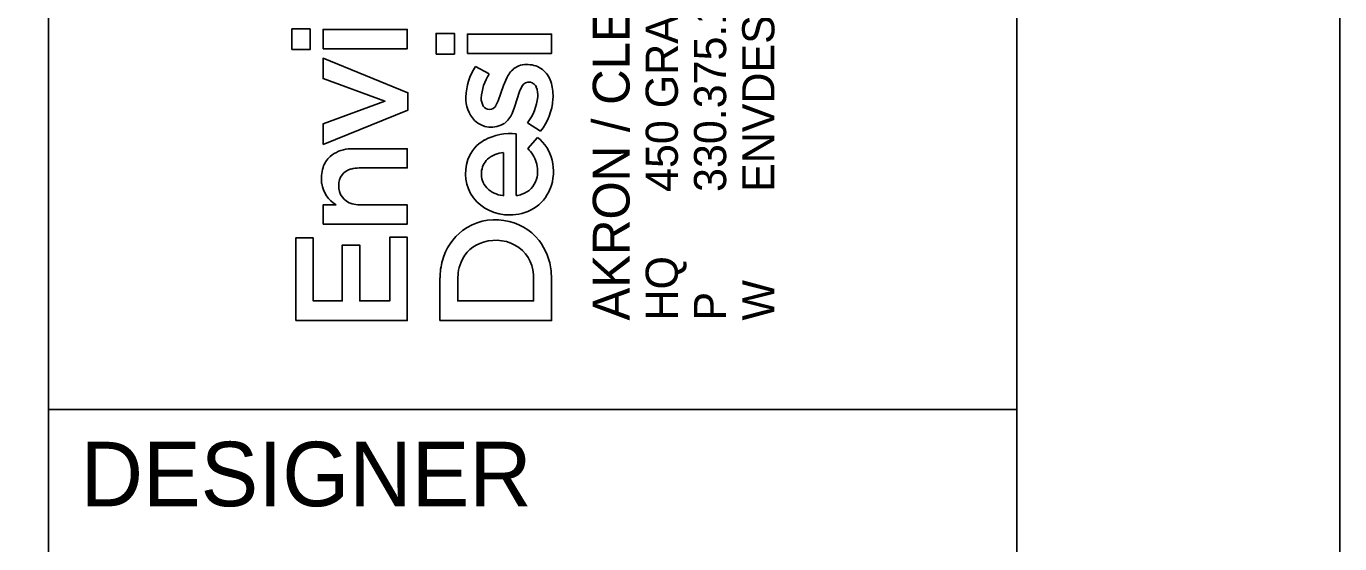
# Model space of a CAD drawing. Extents: x 0 to 34, y 0 to 22.
# Drawn here: x 31.966 to 34, y 2.292 to 3.094 of the extents above; entities that cross this region are included whole.
import ezdxf

# ---------------------------------------------------------------- set-up
doc = ezdxf.new("R2010")
doc.units = 0
for name, color, linetype in [('SH_Border', 7, 'Continuous'), ('SH_Cut_Line', 7, 'Continuous'), ('SH_Data', 7, 'Continuous')]:
    doc.layers.add(name, color=color, linetype=linetype)

msp = doc.modelspace()

# ---------------------------------------------------------------- linework, layer by layer
at = {"layer": 'SH_Border'}
for p, q in [((32, 0.5), (32, 21.5)), ((32, 2.5), (33.5, 2.5))]:
    msp.add_line(p, q, dxfattribs=at)
msp.add_lwpolyline([(1.5, 21.5), (33.5, 21.5), (33.5, 0.5), (1.5, 0.5)], close=True, dxfattribs=at)
at = {"layer": 'SH_Cut_Line'}
msp.add_lwpolyline([(0, 0), (34, 0), (34, 22), (0, 22)], close=True, dxfattribs=at)
at = {"layer": 'SH_Data'}
for p, q in [((32.3771, 3.0582), (32.3771, 3.0903)), ((32.3771, 3.0903), (32.4054, 3.0903)), ((32.4054, 3.0903), (32.4054, 3.0582)), ((32.4254, 3.0594), (32.4254, 3.0893)), ((32.4254, 3.0893), (32.5557, 3.0893)), ((32.5557, 3.0893), (32.5557, 3.0594)), ((32.6005, 3.0511), (32.6005, 3.0832)), ((32.6005, 3.0832), (32.6289, 3.0832)), ((32.6289, 3.0832), (32.6289, 3.0511)), ((32.6489, 3.0523), (32.6489, 3.0822)), ((32.6489, 3.0822), (32.7792, 3.0822)), ((32.7792, 3.0822), (32.7792, 3.0523)), ((32.4054, 3.0582), (32.3771, 3.0582)), ((32.5557, 3.0594), (32.4254, 3.0594)), ((32.7792, 3.0523), (32.6489, 3.0523)), ((32.4254, 3.0133), (32.4254, 3.0446)), ((32.4254, 3.0446), (32.5567, 2.9913)), ((32.6289, 3.0511), (32.6005, 3.0511)), ((32.6615, 3.0321), (32.6827, 3.0203)), ((32.5212, 2.978), (32.4254, 3.0133)), ((32.7048, 3.0026), (32.7104, 3.0153)), ((32.5567, 2.9913), (32.5567, 2.9644)), ((32.6967, 2.9787), (32.7048, 3.0026)), ((32.7298, 2.9933), (32.7221, 2.9688)), ((32.7334, 3.001), (32.7298, 2.9933)), ((32.4254, 2.9429), (32.5212, 2.978)), ((32.693, 2.9712), (32.6967, 2.9787)), ((32.5567, 2.9644), (32.4254, 2.9109)), ((32.7221, 2.9688), (32.7182, 2.9592)), ((32.4254, 2.9109), (32.4254, 2.9429)), ((32.7621, 2.9314), (32.742, 2.9447)), ((32.7245, 2.9275), (32.7246, 2.8319)), ((32.7423, 2.9046), (32.7577, 2.922)), ((32.4644, 2.904), (32.4729, 2.9044)), ((32.4729, 2.9044), (32.5557, 2.9044)), ((32.5557, 2.9044), (32.5557, 2.8746)), ((32.7049, 2.8318), (32.7049, 2.8983)), ((32.5557, 2.8746), (32.4814, 2.8746)), ((32.7036, 2.8317), (32.7049, 2.8318)), ((32.4254, 2.7875), (32.4254, 2.8173)), ((32.4254, 2.8173), (32.4455, 2.8173)), ((32.4822, 2.8173), (32.5557, 2.8173)), ((32.5557, 2.8173), (32.5557, 2.7876)), ((32.5557, 2.7876), (32.4254, 2.7875)), ((32.5286, 2.6683), (32.5286, 2.7672)), ((32.5286, 2.7672), (32.5557, 2.7672)), ((32.5557, 2.7672), (32.5557, 2.6379)), ((32.383, 2.6379), (32.383, 2.766)), ((32.383, 2.766), (32.4101, 2.766)), ((32.4101, 2.766), (32.4101, 2.6683)), ((32.455, 2.6683), (32.455, 2.7549)), ((32.455, 2.7549), (32.4822, 2.7549)), ((32.4822, 2.7549), (32.4822, 2.6683)), ((32.6347, 2.7118), (32.6341, 2.7023)), ((32.7785, 2.715), (32.7792, 2.7021)), ((32.6064, 2.638), (32.6064, 2.704)), ((32.6341, 2.7023), (32.6341, 2.6684)), ((32.7515, 2.6683), (32.7515, 2.7024)), ((32.7792, 2.7021), (32.7792, 2.638)), ((32.4101, 2.6683), (32.455, 2.6683)), ((32.4822, 2.6683), (32.5286, 2.6683)), ((32.6341, 2.6684), (32.7515, 2.6683)), ((32.5557, 2.6379), (32.383, 2.6379)), ((32.7792, 2.638), (32.6064, 2.638))]:
    msp.add_line(p, q, dxfattribs=at)
for points in [[(32.3771, 3.0582), (32.3771, 3.0903), (32.4054, 3.0903), (32.4054, 3.0582)], [(32.4254, 3.0594), (32.4254, 3.0893), (32.5557, 3.0893), (32.5557, 3.0594)], [(32.6005, 3.0511), (32.6005, 3.0832), (32.6289, 3.0832), (32.6289, 3.0511)], [(32.6489, 3.0523), (32.6489, 3.0822), (32.7792, 3.0822), (32.7792, 3.0523)], [(32.4254, 2.9109), (32.4254, 2.9429), (32.5212, 2.978), (32.4254, 3.0133), (32.4254, 3.0446), (32.5567, 2.9913), (32.5567, 2.9644)], [(32.383, 2.6379), (32.383, 2.766), (32.4101, 2.766), (32.4101, 2.6683), (32.455, 2.6683), (32.455, 2.7549), (32.4822, 2.7549), (32.4822, 2.6683), (32.5286, 2.6683), (32.5286, 2.7672), (32.5557, 2.7672), (32.5557, 2.6379)]]:
    msp.add_lwpolyline(points, close=True, dxfattribs=at)
for points in [[(32.6615, 3.0321), (32.6827, 3.0203)], [(32.693, 2.9712), (32.6967, 2.9787), (32.7048, 3.0026), (32.7104, 3.0153)], [(32.7334, 3.001), (32.7298, 2.9933), (32.7221, 2.9688), (32.7182, 2.9592)], [(32.7621, 2.9314), (32.742, 2.9447)], [(32.7245, 2.9275), (32.7246, 2.8319)], [(32.7423, 2.9046), (32.7577, 2.922)], [(32.4644, 2.904), (32.4729, 2.9044), (32.5557, 2.9044), (32.5557, 2.8746), (32.4814, 2.8746)], [(32.7036, 2.8317), (32.7049, 2.8318), (32.7049, 2.8983)], [(32.4254, 2.7875), (32.4254, 2.8173), (32.4455, 2.8173)], [(32.4822, 2.8173), (32.5557, 2.8173), (32.5557, 2.7876), (32.4254, 2.7875)], [(32.7785, 2.715), (32.7792, 2.7021), (32.7792, 2.638), (32.6064, 2.638)], [(32.6347, 2.7118), (32.6341, 2.7023), (32.6341, 2.6684), (32.7515, 2.6683), (32.7515, 2.7024)], [(32.6064, 2.638), (32.6064, 2.704)]]:
    msp.add_lwpolyline(points, dxfattribs=at)
for centre, radius, start, end in [((32.7364, 2.9826), 0.0897, 146.531, 178.7571), ((32.7364, 2.9826), 0.0897, 146.531, 178.7571), ((32.7406, 3.0026), 0.0326, 80.1719, 122.5197), ((32.7406, 3.0026), 0.0326, 80.1719, 122.5197), ((32.7428, 2.9982), 0.0367, 47.7934, 84.6892), ((32.7428, 2.9982), 0.0367, 47.7934, 84.6892), ((32.7452, 2.9789), 0.0749, 146.5112, 176.9101), ((32.7452, 2.9789), 0.0749, 146.5112, 176.9101), ((32.7466, 2.9971), 0.0405, 125.5118, 153.4159), ((32.7466, 2.9971), 0.0405, 125.5118, 153.4159), ((32.7379, 2.9946), 0.0427, 14.9966, 46.2063), ((32.7379, 2.9946), 0.0427, 14.9966, 46.2063), ((32.7438, 2.9963), 0.0114, 76.6609, 155.7053), ((32.7438, 2.9963), 0.0114, 76.6609, 155.7053), ((32.744, 2.9951), 0.0126, 21.5098, 78.5262), ((32.744, 2.9951), 0.0126, 21.5098, 78.5262), ((32.7259, 2.9877), 0.0321, 354.5726, 22.068), ((32.7259, 2.9877), 0.0321, 354.5726, 22.068), ((32.7104, 2.9867), 0.0712, 355.8306, 15.3914), ((32.7104, 2.9867), 0.0712, 355.8306, 15.3914), ((32.6967, 2.9824), 0.0501, 177.5366, 222.7932), ((32.6967, 2.9824), 0.0501, 177.5366, 222.7932), ((32.6931, 2.9823), 0.0228, 178.4747, 211.0868), ((32.6931, 2.9823), 0.0228, 178.4747, 211.0868), ((32.6833, 2.9767), 0.0115, 212.2368, 268.3777), ((32.6833, 2.9767), 0.0115, 212.2368, 268.3777), ((32.6834, 2.9759), 0.0107, 267.716, 333.7337), ((32.6834, 2.9759), 0.0107, 267.716, 333.7337), ((32.6825, 2.9915), 0.0757, 321.811, 354.7969), ((32.6825, 2.9915), 0.0757, 321.811, 354.7969), ((32.6895, 2.9882), 0.0922, 321.9777, 355.8738), ((32.6895, 2.9882), 0.0922, 321.9777, 355.8738), ((32.681, 2.9758), 0.0408, 308.0877, 335.9874), ((32.681, 2.9758), 0.0408, 308.0877, 335.9874), ((32.686, 2.9753), 0.0375, 225.9854, 302.4797), ((32.686, 2.9753), 0.0375, 225.9854, 302.4797), ((32.7024, 2.8691), 0.0558, 118.8308, 160.6244), ((32.7024, 2.8691), 0.0558, 118.8308, 160.6244), ((32.7152, 2.8441), 0.0838, 83.615, 118.2876), ((32.7152, 2.8441), 0.0838, 83.615, 118.2876), ((32.7174, 2.8717), 0.0644, 13.5336, 51.3615), ((32.7174, 2.8717), 0.0644, 13.5336, 51.3615), ((32.4635, 2.8626), 0.0402, 132.2219, 161.6818), ((32.4635, 2.8626), 0.0402, 132.2219, 161.6818), ((32.4687, 2.8543), 0.0499, 94.9696, 130.2225), ((32.4687, 2.8543), 0.0499, 94.9696, 130.2225), ((32.7079, 2.8561), 0.0424, 94.008, 130.8817), ((32.7079, 2.8561), 0.0424, 94.008, 130.8817), ((32.7038, 2.8656), 0.0549, 19.0357, 45.4406), ((32.7038, 2.8656), 0.0549, 19.0357, 45.4406), ((32.4787, 2.8582), 0.056, 162.2736, 187.7919), ((32.4787, 2.8582), 0.056, 162.2736, 187.7919), ((32.4748, 2.8487), 0.025, 103.6865, 182.2187), ((32.4748, 2.8487), 0.025, 103.6865, 182.2187), ((32.4811, 2.8286), 0.046, 89.6049, 105.3284), ((32.4811, 2.8286), 0.046, 89.6049, 105.3284), ((32.7104, 2.8661), 0.0644, 160.5201, 215.7831), ((32.7104, 2.8661), 0.0644, 160.5201, 215.7831), ((32.7005, 2.8663), 0.0298, 132.9851, 177.179), ((32.7005, 2.8663), 0.0298, 132.9851, 177.179), ((32.7107, 2.8697), 0.047, 344.6059, 17.007), ((32.7107, 2.8697), 0.047, 344.6059, 17.007), ((32.7064, 2.8692), 0.0758, 339.3542, 13.3785), ((32.7064, 2.8692), 0.0758, 339.3542, 13.3785), ((32.4703, 2.858), 0.0476, 188.962, 238.7037), ((32.4703, 2.858), 0.0476, 188.962, 238.7037), ((32.7017, 2.865), 0.0311, 175.0013, 223.283), ((32.7017, 2.865), 0.0311, 175.0013, 223.283), ((32.7224, 2.8671), 0.035, 288.0077, 343.5508), ((32.7224, 2.8671), 0.035, 288.0077, 343.5508), ((32.4773, 2.8456), 0.0276, 175.5854, 255.1439), ((32.4773, 2.8456), 0.0276, 175.5854, 255.1439), ((32.7125, 2.8705), 0.0687, 217.7452, 271.6543), ((32.7125, 2.8705), 0.0687, 217.7452, 271.6543), ((32.7089, 2.8736), 0.0423, 225.0619, 262.7974), ((32.7089, 2.8736), 0.0423, 225.0619, 262.7974), ((32.7247, 2.8522), 0.0202, 269.7003, 294.8711), ((32.7247, 2.8522), 0.0202, 269.7003, 294.8711), ((32.7189, 2.8652), 0.0626, 300.9427, 338.7323), ((32.7189, 2.8652), 0.0626, 300.9427, 338.7323), ((32.4818, 2.8595), 0.0422, 254.0916, 270.5284), ((32.4818, 2.8595), 0.0422, 254.0916, 270.5284), ((32.7155, 2.8724), 0.0706, 269.2048, 300.3341), ((32.7155, 2.8724), 0.0706, 269.2048, 300.3341), ((32.6923, 2.7079), 0.0864, 81.194, 125.9984), ((32.6923, 2.7079), 0.0864, 81.194, 125.9984), ((32.6946, 2.7113), 0.0827, 37.8521, 82.402), ((32.6946, 2.7113), 0.0827, 37.8521, 82.402), ((32.6939, 2.7089), 0.0865, 127.2362, 165.148), ((32.6939, 2.7089), 0.0865, 127.2362, 165.148), ((32.6889, 2.7078), 0.054, 106.1881, 157.3861), ((32.6889, 2.7078), 0.054, 106.1881, 157.3861), ((32.6928, 2.6986), 0.0639, 55.6727, 107.2093), ((32.6928, 2.6986), 0.0639, 55.6727, 107.2093), ((32.6929, 2.705), 0.0587, 357.4662, 52.2665), ((32.6929, 2.705), 0.0587, 357.4662, 52.2665), ((32.6859, 2.7057), 0.0931, 5.7333, 37.304), ((32.6859, 2.7057), 0.0931, 5.7333, 37.304), ((32.7143, 2.7028), 0.1078, 164.7861, 179.3704), ((32.7143, 2.7028), 0.1078, 164.7861, 179.3704), ((32.6983, 2.7039), 0.0641, 157.3571, 172.9275), ((32.6983, 2.7039), 0.0641, 157.3571, 172.9275)]:
    msp.add_arc(centre, radius, start, end, dxfattribs=at)

# ---------------------------------------------------------------- texts
for s, height, p in [('450 GRANT ST., AKRON, OH  44311', 0.049846, (32.9749, 2.8374)), ('AKRON / CLEVELAND / COLUMBUS', 0.056969, (32.9001, 2.638)), ('ENVDESIGNGROUP.COM', 0.049846, (33.1244, 2.8374)), ('330.375.1390', 0.049846, (33.0497, 2.8374)), ('HQ ', 0.04985, (32.9749, 2.638)), ('W', 0.0498, (33.1244, 2.638)), ('P', 0.0498, (33.0497, 2.638))]:
    msp.add_text(s, height=height, rotation=90, dxfattribs=at).set_placement(p)
msp.add_text('DESIGNER', height=0.1, dxfattribs=at).set_placement((32.05, 2.35))

doc.saveas('drawing.dxf')
